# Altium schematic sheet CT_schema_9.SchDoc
size 147 x 119 mm
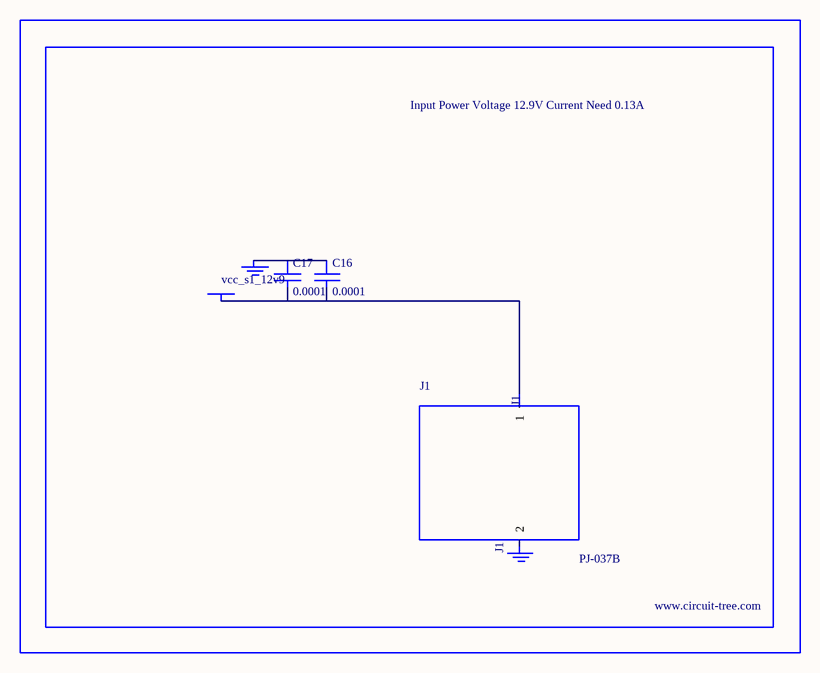
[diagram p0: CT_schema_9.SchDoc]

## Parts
BORDER8  (no value)
C16  0.0001  [EXV-9H]
C17  0.0001  [EXV-9H]
GND_INSTANCE_8_0  (no value)
GND_INSTANCE_8_1  (no value)
J1  PJ-037B  [PJ-037B_PACKAGE]
POWER_INSTANCE_8_0  vcc_s1_12v9

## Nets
NetC16_1: C16.1 C17.1 GND_INSTANCE_8_0.0(GND)
NetC16_2: C16.2 C17.2 J1.1 POWER_INSTANCE_8_0.0(PWR)

Not connected (* = marked no-connect by the designer): GND_INSTANCE_8_1 0(GND); J1 2

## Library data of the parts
BORDER8 = BORDER_PAGE8
C16 C17 = EDK107M035A9HAA
GND_INSTANCE_8_0 GND_INSTANCE_8_1 = GND
POWER_INSTANCE_8_0 = PWR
